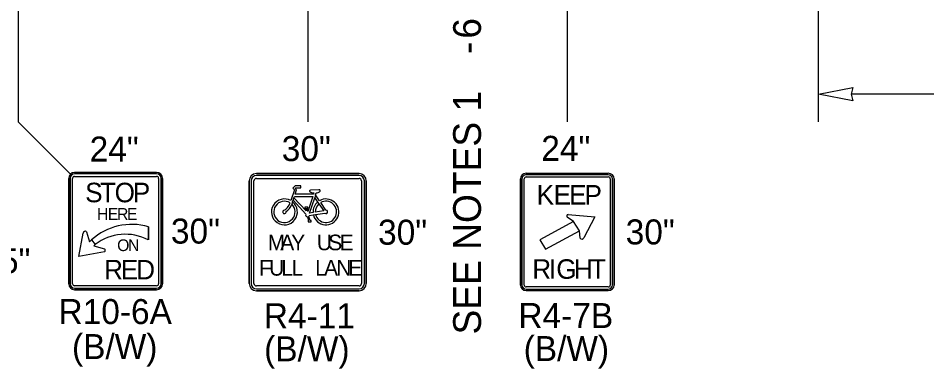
# Model space of a CAD drawing. Extents: x 99976 to 100136, y 99905 to 100011.
# Drawn here: x 100049.858 to 100052.474, y 99945.128 to 99946.138 of the extents above; entities that cross this region are included whole.
import ezdxf

# ---------------------------------------------------------------- set-up
doc = ezdxf.new("R2010")
doc.units = 0
for name, color, linetype in [('TR_SN_ConstructionSigns', 7, 'Continuous'), ('TR_WZ_WorkZoneDetails', 7, 'Continuous'), ('TR_WZ_WorkZoneTextCurrent', 7, 'Continuous')]:
    doc.layers.add(name, color=color, linetype=linetype)

msp = doc.modelspace()

# ---------------------------------------------------------------- linework, layer by layer
at = {"layer": 'TR_SN_ConstructionSigns'}
for p, q in [((100050.0031, 99945.6769), (100050.0031, 99945.3731)), ((100050.0031, 99945.3731), (100050.0031, 99945.6769)), ((100050.0031, 99945.6769), (100050.0031, 99945.3731)), ((100050.0031, 99945.3731), (100050.0031, 99945.6769)), ((100050.0073, 99945.6769), (100050.0073, 99945.3731)), ((100050.0144, 99945.3731), (100050.0144, 99945.6769)), ((100050.2562, 99945.6938), (100050.02, 99945.6938)), ((100050.02, 99945.6938), (100050.2562, 99945.6938)), ((100050.2562, 99945.6938), (100050.02, 99945.6938)), ((100050.02, 99945.6938), (100050.2562, 99945.6938)), ((100050.2562, 99945.6895), (100050.02, 99945.6895)), ((100050.02, 99945.6825), (100050.2562, 99945.6825)), ((100050.2619, 99945.6769), (100050.2619, 99945.3731)), ((100050.2689, 99945.3731), (100050.2689, 99945.6769)), ((100050.2731, 99945.3731), (100050.2731, 99945.6769)), ((100050.2731, 99945.6769), (100050.2731, 99945.3731)), ((100050.2731, 99945.3731), (100050.2731, 99945.6769)), ((100050.2731, 99945.6769), (100050.2731, 99945.3731)), ((100050.5435, 99945.6906), (100050.8388, 99945.6906)), ((100050.8388, 99945.6906), (100050.5435, 99945.6906)), ((100050.8388, 99945.6906), (100050.5435, 99945.6906)), ((100050.8388, 99945.6849), (100050.5435, 99945.6849)), ((100050.5435, 99945.6765), (100050.8388, 99945.6765)), ((100051.3202, 99945.6913), (100051.5565, 99945.6913)), ((100051.5565, 99945.6913), (100051.3202, 99945.6913)), ((100051.5565, 99945.6869), (100051.3202, 99945.6869)), ((100051.3202, 99945.6808), (100051.5565, 99945.6808)), ((100050.5224, 99945.3742), (100050.5224, 99945.6695)), ((100050.5224, 99945.6695), (100050.5224, 99945.3742)), ((100050.5224, 99945.6695), (100050.5224, 99945.3742)), ((100050.528, 99945.6695), (100050.528, 99945.3742)), ((100050.5365, 99945.3742), (100050.5365, 99945.6695)), ((100050.6552, 99945.6554), (100050.6482, 99945.6484)), ((100050.6716, 99945.6554), (100050.6552, 99945.6554)), ((100050.6716, 99945.6499), (100050.6716, 99945.6554)), ((100050.8458, 99945.6695), (100050.8458, 99945.3742)), ((100050.8543, 99945.3742), (100050.8543, 99945.6695)), ((100050.8599, 99945.6695), (100050.8599, 99945.3742)), ((100050.8599, 99945.3742), (100050.8599, 99945.6695)), ((100050.8599, 99945.3742), (100050.8599, 99945.6695)), ((100051.3034, 99945.3696), (100051.3034, 99945.6755)), ((100051.3034, 99945.6755), (100051.3034, 99945.3696)), ((100051.308, 99945.6755), (100051.308, 99945.3696)), ((100051.3146, 99945.3696), (100051.3146, 99945.6755)), ((100051.5621, 99945.6755), (100051.5621, 99945.3696)), ((100051.5687, 99945.3696), (100051.5687, 99945.6755)), ((100051.5734, 99945.6755), (100051.5734, 99945.3696)), ((100051.5734, 99945.3696), (100051.5734, 99945.6755)), ((100050.6528, 99945.6438), (100050.6425, 99945.6127)), ((100050.6482, 99945.6484), (100050.6528, 99945.6438)), ((100050.6516, 99945.6209), (100050.6529, 99945.6247)), ((100050.6529, 99945.6247), (100050.7055, 99945.6247)), ((100050.6551, 99945.6313), (100050.6592, 99945.6438)), ((100050.7077, 99945.6313), (100050.6551, 99945.6313)), ((100050.6553, 99945.6478), (100050.6574, 99945.6499)), ((100050.6592, 99945.6438), (100050.6553, 99945.6478)), ((100050.6574, 99945.6499), (100050.6716, 99945.6499)), ((100050.7055, 99945.6247), (100050.6911, 99945.5814)), ((100050.7235, 99945.6442), (100050.6987, 99945.6425)), ((100050.7088, 99945.6347), (100050.7077, 99945.6313)), ((100050.7138, 99945.629), (100050.7112, 99945.6211)), ((100050.7138, 99945.629), (100050.7158, 99945.6348)), ((100050.725, 99945.6125), (100050.7138, 99945.629)), ((100050.6477, 99945.6091), (100050.6454, 99945.6023)), ((100050.6477, 99945.6091), (100050.6492, 99945.6138)), ((100050.6492, 99945.6138), (100050.6516, 99945.6209)), ((100050.6492, 99945.6138), (100050.6859, 99945.574)), ((100050.6863, 99945.5833), (100050.6516, 99945.6209)), ((100050.6965, 99945.5769), (100050.7112, 99945.6211)), ((100050.7112, 99945.6211), (100050.7196, 99945.6087)), ((100050.7196, 99945.6087), (100050.7234, 99945.6032)), ((100050.7234, 99945.6032), (100050.7372, 99945.5829)), ((100050.7436, 99945.5851), (100050.7287, 99945.607)), ((100050.6915, 99945.594), (100050.6828, 99945.594)), ((100050.6849, 99945.5907), (100050.6863, 99945.5833)), ((100050.6911, 99945.5814), (100050.6894, 99945.5907)), ((100050.6894, 99945.5907), (100050.6915, 99945.5907)), ((100050.6915, 99945.5907), (100050.6915, 99945.594)), ((100050.696, 99945.5702), (100050.7073, 99945.5718)), ((100050.7064, 99945.5783), (100050.6965, 99945.5769)), ((100050.7073, 99945.5718), (100050.7139, 99945.5728)), ((100050.7372, 99945.5829), (100050.713, 99945.5793)), ((100050.7139, 99945.5728), (100050.7402, 99945.5767)), ((100051.4407, 99945.5725), (100051.5177, 99945.5656)), ((100050.6902, 99945.5659), (100050.6938, 99945.5551)), ((100050.6938, 99945.5551), (100050.692, 99945.5551)), ((100050.692, 99945.5551), (100050.692, 99945.5518)), ((100050.692, 99945.5518), (100050.7007, 99945.5518)), ((100050.6984, 99945.5551), (100050.6943, 99945.5673)), ((100050.7007, 99945.5551), (100050.6984, 99945.5551)), ((100050.7007, 99945.5518), (100050.7007, 99945.5551)), ((100051.4567, 99945.5529), (100051.359, 99945.5)), ((100051.4567, 99945.5529), (100051.4382, 99945.5647)), ((100051.4736, 99945.5255), (100051.4567, 99945.5529)), ((100051.4736, 99945.5255), (100051.4567, 99945.5529)), ((100051.4567, 99945.5529), (100051.4567, 99945.5529)), ((100051.5177, 99945.5656), (100051.4863, 99945.506)), ((100050.0546, 99945.5232), (100050.0631, 99945.4941)), ((100050.2326, 99945.5374), (100050.2323, 99945.4996)), ((100050.2323, 99945.4996), (100050.2326, 99945.5374)), ((100051.3758, 99945.4726), (100051.4736, 99945.5255)), ((100051.4752, 99945.5045), (100051.4736, 99945.5255)), ((100051.4736, 99945.5255), (100051.4736, 99945.5255)), ((100050.0326, 99945.4519), (100050.0449, 99945.5189)), ((100050.0631, 99945.4941), (100050.0688, 99945.4998)), ((100050.0688, 99945.4998), (100050.0793, 99945.4864)), ((100050.0688, 99945.4998), (100050.0793, 99945.4864)), ((100051.359, 99945.5), (100051.3758, 99945.4726)), ((100050.0793, 99945.4864), (100050.075, 99945.4821)), ((100050.075, 99945.4821), (100050.1058, 99945.4738)), ((100050.1057, 99945.4655), (100050.0326, 99945.4519)), ((100050.2562, 99945.3675), (100050.02, 99945.3675)), ((100050.8388, 99945.3671), (100050.5435, 99945.3671)), ((100051.5565, 99945.3644), (100051.3202, 99945.3644)), ((100050.02, 99945.3605), (100050.2562, 99945.3605)), ((100050.02, 99945.3563), (100050.2562, 99945.3563)), ((100050.2562, 99945.3563), (100050.02, 99945.3563)), ((100050.02, 99945.3563), (100050.2562, 99945.3563)), ((100050.2562, 99945.3563), (100050.02, 99945.3563)), ((100050.5435, 99945.3587), (100050.8388, 99945.3587)), ((100050.8388, 99945.3531), (100050.5435, 99945.3531)), ((100050.5435, 99945.3531), (100050.8388, 99945.3531)), ((100050.5435, 99945.3531), (100050.8388, 99945.3531)), ((100051.3202, 99945.3582), (100051.5565, 99945.3582)), ((100051.5565, 99945.3538), (100051.3202, 99945.3538)), ((100051.3202, 99945.3538), (100051.5565, 99945.3538))]:
    msp.add_line(p, q, dxfattribs=at)
msp.add_lwpolyline([(100050.6828, 99945.594), (100050.6828, 99945.5907), (100050.6849, 99945.5907)], dxfattribs=at)
for centre, radius, start, end in [((100050.02, 99945.6769), 0.0169, 90, 180), ((100050.02, 99945.6769), 0.0169, 90, 180), ((100050.02, 99945.6769), 0.0169, 90, 180), ((100050.02, 99945.6769), 0.0169, 90, 180), ((100050.02, 99945.6769), 0.0127, 90, 180), ((100050.02, 99945.6769), 0.00562, 90, 180), ((100050.2562, 99945.6769), 0.0169, 0, 90), ((100050.2562, 99945.6769), 0.0169, 0, 90), ((100050.2562, 99945.6769), 0.0169, 0, 90), ((100050.2562, 99945.6769), 0.0169, 0, 90), ((100050.2562, 99945.6769), 0.0127, 0, 90), ((100050.2562, 99945.6769), 0.00562, 0, 90), ((100050.5435, 99945.6695), 0.0211, 90, 180), ((100050.5435, 99945.6695), 0.0211, 90, 180), ((100050.5435, 99945.6695), 0.0211, 90, 180), ((100050.5435, 99945.6695), 0.0155, 90, 180), ((100050.5435, 99945.6695), 0.00703, 90, 180), ((100050.8388, 99945.6695), 0.0211, 0, 90), ((100050.8388, 99945.6695), 0.0211, 0, 90), ((100050.8388, 99945.6695), 0.0211, 0, 90), ((100050.8388, 99945.6695), 0.0155, 0, 90), ((100050.8388, 99945.6695), 0.00703, 0, 90), ((100050.6987, 99945.6403), 0.00219, 89.3854, 243.6828), ((100050.7239, 99945.6409), 0.00329, 294.5519, 96.4128), ((100050.6241, 99945.5802), 0.0373, 60.5529, 50.868), ((100050.6241, 99945.5802), 0.0307, 58.1532, 46.1649), ((100050.7437, 99945.5802), 0.0373, 130.0889, 182.8379), ((100050.7437, 99945.5802), 0.0373, 192.9622, 119.9648), ((100050.7437, 99945.5802), 0.0307, 131.3616, 181.6359), ((100050.7437, 99945.5802), 0.0307, 193.937, 119.0598), ((100050.6241, 99945.5802), 0.00493, 105.257, 14.3233), ((100050.6907, 99945.5714), 0.00548, 151.1744, 264.8566), ((100050.7437, 99945.5802), 0.00493, 225.1095, 90.4672), ((100050.6907, 99945.5714), 0.00548, 312.0053, 347.2932), ((100050.1842, 99945.3725), 0.1718, 73.6434, 132.2131), ((100050.1842, 99945.3725), 0.1718, 73.6434, 132.2131), ((100050.1662, 99945.3731), 0.1427, 62.4149, 127.4769), ((100050.1662, 99945.3731), 0.1427, 62.4149, 127.4769), ((100050.02, 99945.3731), 0.0169, 180, 270), ((100050.02, 99945.3731), 0.0169, 180, 270), ((100050.02, 99945.3731), 0.0169, 180, 270), ((100050.02, 99945.3731), 0.0169, 180, 270), ((100050.02, 99945.3731), 0.0127, 180, 270), ((100050.02, 99945.3731), 0.00562, 180, 270), ((100050.2562, 99945.3731), 0.0169, 270, 0), ((100050.2562, 99945.3731), 0.0169, 270, 0), ((100050.2562, 99945.3731), 0.0169, 270, 0), ((100050.2562, 99945.3731), 0.0127, 270, 0), ((100050.2562, 99945.3731), 0.00562, 270, 0), ((100050.2562, 99945.3731), 0.0169, 270, 0), ((100050.5435, 99945.3742), 0.0211, 180, 270), ((100050.5435, 99945.3742), 0.0211, 180, 270), ((100050.5435, 99945.3742), 0.0211, 180, 270), ((100050.5435, 99945.3742), 0.0155, 180, 270), ((100050.5435, 99945.3742), 0.00703, 180, 270), ((100050.8388, 99945.3742), 0.0211, 270, 0), ((100050.8388, 99945.3742), 0.0211, 270, 0), ((100050.8388, 99945.3742), 0.0155, 270, 0), ((100050.8388, 99945.3742), 0.00703, 270, 0), ((100050.8388, 99945.3742), 0.0211, 270, 0)]:
    msp.add_arc(centre, radius, start, end, dxfattribs=at)
for centre, major_axis, ratio, start_param, end_param in [((100051.3202, 99945.6755), (-0.0169, 0), 0.9375, 4.712389, 6.283185), ((100051.3202, 99945.6755), (-0.0169, 0), 0.9375, 4.712389, 6.283185), ((100051.3202, 99945.6755), (0.0122, 0), 0.9375, 1.570796, 3.141593), ((100051.3202, 99945.6755), (0.00563, 0), 0.9375, 1.570796, 3.141593), ((100051.5565, 99945.6755), (-0.0169, 0), 0.9375, 3.141593, 4.712389), ((100051.5565, 99945.6755), (-0.0169, 0), 0.9375, 3.141593, 4.712389), ((100051.5565, 99945.6755), (0.0122, 0), 0.9375, 0, 1.570796), ((100051.5565, 99945.6755), (0.00562, 0), 0.9375, 6.283185, 7.853982), ((100050.7118, 99945.6455), (-0.0186, 0), 0.588235, 0.686048, 1.410588), ((100050.7118, 99945.6455), (-0.0186, 0), 0.588235, 1.786993, 2.401245), ((100050.629, 99945.6009), (-0.0105, -0.0158), 0.413554, 0.494612, 2.170849), ((100050.629, 99945.6009), (-0.014, -0.021), 0.55814, 0.868091, 1.989998), ((100051.4415, 99945.568), (0.00485, -0.00001), 0.937492, 1.73335, 3.955171), ((100050.0507, 99945.519), (-0.00583, -0.00008), 0.989437, 3.962549, 6.283185), ((100051.4804, 99945.5075), (0.00607, -0.00002), 0.9368, 3.700197, 6.020834), ((100050.1037, 99945.4697), (-0.00414, 0.00215), 0.999053, 2.490568, 4.712389), ((100051.3202, 99945.3696), (0.0169, 0), 0.9375, 3.141593, 4.712389), ((100051.3202, 99945.3696), (0.0169, 0), 0.9375, 3.141593, 4.712389), ((100051.3202, 99945.3696), (0.0122, 0), 0.9375, 3.141593, 4.712389), ((100051.3202, 99945.3696), (0.00563, 0), 0.9375, 3.141593, 4.712389), ((100051.5565, 99945.3696), (0.0169, 0), 0.9375, 4.712389, 6.283185), ((100051.5565, 99945.3696), (0.0122, 0), 0.9375, 4.712389, 6.283185), ((100051.5565, 99945.3696), (0.00562, 0), 0.9375, 4.712389, 6.283185), ((100051.5565, 99945.3696), (0.0169, 0), 0.9375, 4.712389, 6.283185)]:
    msp.add_ellipse(centre, major_axis=major_axis, ratio=ratio, start_param=start_param, end_param=end_param, dxfattribs=at)
at = {"layer": 'TR_WZ_WorkZoneDetails'}
for p, q in [((100049.8576, 99946.3347), (100049.8576, 99945.8393)), ((100051.4384, 99946.2797), (100051.4384, 99945.8393)), ((100050.6914, 99946.2577), (100050.6914, 99945.8393)), ((100052.1619, 99945.8393), (100052.1619, 99946.2193)), ((100052.9532, 99945.9193), (100052.2556, 99945.9193)), ((100049.8576, 99945.8393), (100050.008, 99945.6888))]:
    msp.add_line(p, q, dxfattribs=at)
msp.add_lwpolyline([(100052.1619, 99945.9193), (100052.2602, 99945.9386), (100052.2556, 99945.9193), (100052.2602, 99945.9)], close=True, dxfattribs=at)

# ---------------------------------------------------------------- texts
at = {"layer": 'TR_SN_ConstructionSigns'}
for s, p in [('24"', (100050.0633, 99945.7253)), ('30"', (100050.6164, 99945.7266)), ('24"', (100051.3636, 99945.7273)), ('30"', (100050.2973, 99945.489)), ('30"', (100050.8937, 99945.4858)), ('30"', (100051.6066, 99945.4866)), ('15"', (100049.7516, 99945.4035)), ('R10-6A', (100049.9737, 99945.2573)), ('R4-11', (100050.5649, 99945.2451)), ('R4-7B', (100051.2977, 99945.2458)), ('(B/W)', (100050.0125, 99945.1565)), ('(B/W)', (100050.5657, 99945.15)), ('(B/W)', (100051.3128, 99945.1507))]:
    msp.add_text(s, height=0.072, rotation=360, dxfattribs=at).set_placement(p)
for s, height, p in [('S', 0.0562, (100050.0504, 99945.608)), ('T', 0.0562, (100050.0931, 99945.608)), ('O', 0.0562, (100050.1353, 99945.608)), ('P', 0.0562, (100050.1876, 99945.608)), ('K', 0.0562, (100051.3503, 99945.6013)), ('E', 0.0562, (100051.3993, 99945.6013)), ('E', 0.0562, (100051.4437, 99945.6013)), ('P', 0.0562, (100051.4881, 99945.6013)), ('H', 0.0338, (100050.0844, 99945.5574)), ('E', 0.0338, (100050.1155, 99945.5574)), ('R', 0.0338, (100050.1422, 99945.5574)), ('E', 0.0338, (100050.1708, 99945.5574)), ('O', 0.0338, (100050.1425, 99945.4674)), ('N', 0.0338, (100050.1739, 99945.4674)), ('M', 0.045, (100050.5762, 99945.4698)), ('A', 0.045, (100050.6122, 99945.4698)), ('Y', 0.045, (100050.6437, 99945.4698)), ('U', 0.045, (100050.7175, 99945.4698)), ('S', 0.045, (100050.7503, 99945.4698)), ('E', 0.045, (100050.7832, 99945.4698)), ('R', 0.0562, (100050.105, 99945.3858)), ('E', 0.0562, (100050.1529, 99945.3858)), ('D', 0.0562, (100050.1973, 99945.3858)), ('F', 0.045, (100050.551, 99945.3967)), ('U', 0.045, (100050.5802, 99945.3967)), ('L', 0.045, (100050.6153, 99945.3967)), ('L', 0.045, (100050.6446, 99945.3967)), ('L', 0.045, (100050.7125, 99945.3967)), ('A', 0.045, (100050.7382, 99945.3967)), ('N', 0.045, (100050.7733, 99945.3967)), ('E', 0.045, (100050.8084, 99945.3967)), ('R', 0.0562, (100051.3377, 99945.3876)), ('I', 0.0562, (100051.3855, 99945.3876)), ('G', 0.0562, (100051.4069, 99945.3876)), ('H', 0.0562, (100051.4575, 99945.3876)), ('T', 0.0562, (100051.5042, 99945.3876))]:
    msp.add_text(s, height=height, dxfattribs=at).set_placement(p)
at = {"layer": 'TR_WZ_WorkZoneTextCurrent'}
for s, p in [('6', (100051.1899, 99946.079)), ('-', (100051.1899, 99946.0349)), ('SEE NOTES 1', (100051.1899, 99945.2272))]:
    msp.add_text(s, height=0.08, rotation=90, dxfattribs=at).set_placement(p)

doc.saveas('drawing.dxf')
